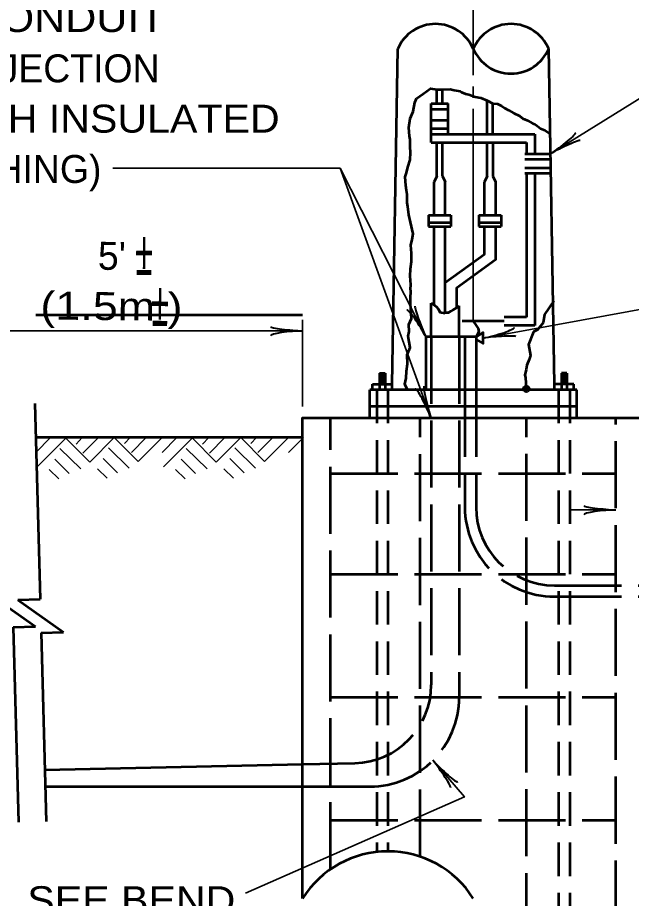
# Model space of a CAD drawing. Extents: x -68 to 612, y -58 to 382.
# Drawn here: x 153.4 to 208.3, y 135 to 213.8 of the extents above; entities that cross this region are included whole.
import ezdxf
from ezdxf.enums import TextEntityAlignment as Align

# ---------------------------------------------------------------- set-up
doc = ezdxf.new("R2010")
doc.units = 0
doc.header["$PDMODE"] = 32
doc.header["$PDSIZE"] = 0.5
doc.linetypes.add('LONG_DASHED', pattern=[7.5, 6, -1.5])
doc.linetypes.add('MEDIUM_DASHED', pattern=[4.5, 3, -1.5])
doc.layers.add('1', color=7, linetype='Continuous', lineweight=53)

msp = doc.modelspace()

# ---------------------------------------------------------------- linework, layer by layer
at = {"layer": '1', "lineweight": 35}
for p, q in [((194.116, 223.64), (194.116, 208.64)), ((194.116, 207.64), (194.116, 206.64)), ((194.116, 205.64), (194.116, 186.64)), ((182.206, 200.326), (161.911, 200.326)), ((195.016, 185.14), (221.485, 189.97)), ((178.866, 179.015), (178.866, 186.775)), ((147.007, 185.775), (178.866, 185.775)), ((156.327, 176.235), (155.007, 174.915)), ((157.747, 176.235), (155.127, 173.615)), ((157.647, 176.235), (159.847, 174.035)), ((159.167, 176.235), (158.607, 175.655)), ((160.607, 176.235), (159.227, 174.855)), ((162.027, 176.235), (159.847, 174.035)), ((162.027, 176.235), (164.167, 174.095)), ((163.447, 176.235), (162.927, 175.715)), ((164.887, 176.235), (163.567, 174.915)), ((166.307, 176.235), (164.167, 174.095)), ((167.627, 176.235), (166.307, 174.915)), ((169.047, 176.235), (166.427, 173.615)), ((168.947, 176.235), (171.147, 174.035)), ((170.467, 176.235), (169.907, 175.655)), ((171.907, 176.235), (170.527, 174.855)), ((173.327, 176.235), (171.147, 174.035)), ((173.327, 176.235), (175.467, 174.095)), ((174.747, 176.235), (174.227, 175.715)), ((176.187, 176.235), (174.867, 174.915)), ((177.607, 176.235), (175.467, 174.095)), ((178.927, 176.235), (177.607, 174.915)), ((157.167, 175.275), (159.027, 173.435)), ((161.507, 175.335), (163.347, 173.495)), ((168.467, 175.275), (170.327, 173.435)), ((172.807, 175.335), (174.647, 173.495)), ((156.707, 174.315), (157.987, 173.035)), ((161.047, 174.375), (162.327, 173.095)), ((168.007, 174.315), (169.287, 173.035)), ((172.347, 174.375), (173.627, 173.095)), ((156.207, 173.395), (157.067, 172.555)), ((160.527, 173.455), (161.387, 172.595)), ((167.507, 173.395), (168.367, 172.555)), ((171.827, 173.455), (172.687, 172.595)), ((206.866, 169.764), (202.866, 169.764))]:
    msp.add_line(p, q, dxfattribs=at)
at = {"layer": '1'}
for p, q in [((186.866, 181.015), (187.366, 211.015)), ((201.366, 181.015), (200.866, 211.015)), ((190.866, 206.126), (190.866, 207.376)), ((191.366, 206.126), (191.366, 207.376)), ((190.366, 202.626), (190.366, 206.126)), ((190.366, 206.126), (191.866, 206.126)), ((190.366, 205.626), (191.866, 205.626)), ((191.866, 203.376), (191.866, 206.126)), ((195.366, 203.376), (195.366, 206.376)), ((195.866, 203.376), (195.866, 206.126)), ((190.366, 204.623), (191.866, 204.623)), ((190.366, 203.876), (191.866, 203.876)), ((190.366, 203.376), (199.616, 203.376)), ((199.616, 203.376), (199.616, 201.626)), ((190.366, 202.626), (198.866, 202.626)), ((190.866, 199.626), (190.866, 202.626)), ((191.366, 199.626), (191.366, 202.626)), ((195.366, 199.626), (195.366, 202.626)), ((195.866, 202.626), (195.866, 199.626)), ((198.866, 202.626), (198.866, 201.626)), ((198.741, 201.626), (201.023, 201.626)), ((198.741, 201.126), (201.023, 201.126)), ((198.741, 200.376), (201.023, 200.376)), ((190.866, 199.626), (190.616, 199.126)), ((191.366, 199.626), (191.616, 199.126)), ((195.366, 199.626), (195.116, 199.126)), ((195.866, 199.626), (196.116, 199.126)), ((198.741, 199.876), (201.023, 199.876)), ((198.866, 199.876), (198.866, 187.015)), ((199.616, 199.876), (199.616, 186.265)), ((190.616, 196.126), (190.616, 199.126)), ((191.616, 196.126), (191.616, 199.126)), ((195.116, 196.126), (195.116, 199.126)), ((196.116, 199.126), (196.116, 196.126)), ((190.116, 196.126), (192.116, 196.126)), ((190.116, 196.126), (190.116, 195.126)), ((190.116, 195.47), (192.116, 195.47)), ((192.116, 196.126), (192.116, 195.126)), ((194.616, 196.126), (196.616, 196.126)), ((194.616, 196.126), (194.616, 195.126)), ((194.616, 195.47), (196.616, 195.47)), ((196.616, 196.126), (196.616, 195.126)), ((190.116, 195.126), (190.616, 195.126)), ((190.616, 195.126), (192.116, 195.126)), ((190.616, 188.122), (190.616, 195.126)), ((191.616, 187.381), (191.616, 195.126)), ((194.616, 195.126), (195.116, 195.126)), ((190.366, 185.265), (190.366, 188.265)), ((192.616, 187.848), (192.866, 188.015)), ((192.866, 185.265), (192.866, 188.015)), ((155.007, 187.207), (178.866, 187.207)), ((198.866, 187.015), (196.866, 187.015)), ((196.866, 186.64), (193.116, 186.64)), ((199.616, 186.265), (196.866, 186.265)), ((193.366, 185.265), (193.366, 180.515)), ((194.366, 185.265), (194.366, 180.515)), ((185.741, 182.015), (185.741, 180.515)), ((185.741, 182.015), (186.241, 182.015)), ((186.241, 182.015), (186.241, 180.515)), ((201.991, 182.015), (201.991, 180.515)), ((202.491, 182.015), (201.991, 182.015)), ((202.491, 182.015), (202.491, 180.515)), ((185.741, 181.765), (186.241, 181.765)), ((185.741, 181.515), (186.241, 181.515)), ((185.741, 181.265), (186.241, 181.265)), ((185.866, 181.89), (186.116, 181.89)), ((185.866, 181.64), (186.116, 181.64)), ((185.866, 181.39), (186.116, 181.39)), ((202.491, 181.765), (201.991, 181.765)), ((202.491, 181.515), (201.991, 181.515)), ((202.491, 181.265), (201.991, 181.265)), ((202.366, 181.89), (202.116, 181.89)), ((202.366, 181.64), (202.116, 181.64)), ((202.366, 181.39), (202.116, 181.39)), ((184.866, 178.015), (184.866, 180.515)), ((203.366, 180.515), (184.866, 180.515)), ((185.116, 180.515), (185.116, 181.015)), ((185.116, 181.015), (186.866, 181.015)), ((185.866, 181.14), (186.116, 181.14)), ((186.866, 180.515), (186.866, 181.015)), ((201.366, 180.515), (201.366, 181.015)), ((203.116, 181.015), (201.366, 181.015)), ((202.366, 181.14), (202.116, 181.14)), ((203.116, 180.515), (203.116, 181.015)), ((203.366, 178.015), (203.366, 180.515)), ((154.925, 179.274), (155.406, 161.775)), ((203.366, 179.015), (184.866, 179.015)), ((155.007, 176.275), (178.866, 176.275)), ((150.893, 162.22), (154.974, 159.331)), ((153.406, 161.72), (155.406, 161.775)), ((153.406, 161.72), (157.487, 158.831)), ((152.974, 159.276), (154.974, 159.331)), ((152.974, 159.276), (153.454, 141.839)), ((155.488, 158.776), (157.487, 158.831)), ((155.488, 158.776), (155.952, 141.908)), ((155.825, 146.525), (178.866, 147.025)), ((155.866, 145.025), (178.866, 145.025))]:
    msp.add_line(p, q, dxfattribs=at)
at = {"layer": '1', "linetype": 'LONG_DASHED'}
for p, q in [((190.366, 185.265), (190.366, 154.125)), ((192.866, 185.265), (192.866, 153.025)), ((193.366, 180.515), (193.366, 170.015)), ((194.366, 180.515), (194.366, 170.015)), ((181.366, 137.634), (181.366, 178.015)), ((189.366, 138.762), (189.366, 178.015)), ((198.866, 131.289), (198.866, 178.015)), ((206.866, 132.417), (206.866, 178.015)), ((181.366, 173.015), (206.866, 173.015)), ((181.366, 164.015), (206.866, 164.015)), ((201.366, 163.015), (209.366, 163.015)), ((201.366, 162.015), (209.366, 162.015)), ((181.366, 153.015), (206.866, 153.015)), ((178.866, 147.025), (183.518, 147.126)), ((178.866, 145.025), (184.866, 145.025)), ((181.366, 142.015), (206.866, 142.015))]:
    msp.add_line(p, q, dxfattribs=at)
at = {"layer": '1', "linetype": 'MEDIUM_DASHED'}
for p, q in [((185.491, 180.515), (185.491, 139.177)), ((186.491, 180.515), (186.491, 139.233)), ((201.741, 180.515), (201.741, 130.818)), ((202.741, 180.515), (202.741, 130.873))]:
    msp.add_line(p, q, dxfattribs=at)
at = {"layer": '1', "lineweight": 35}
for points in [[(201.023, 201.626), (213.267, 209.222), (216.001, 209.222)], [(189.866, 185.265), (182.206, 200.326), (190.322, 178.015)], [(190.523, 147.369), (193.33, 144.099), (173.761, 135.499)]]:
    msp.add_lwpolyline(points, dxfattribs=at)
at = {"layer": '1'}
for points in [[(188.233, 180.517), (188.001, 181.02), (188.117, 181.561), (188.156, 182.179), (188.233, 182.836), (188.194, 183.648), (188.465, 184.305), (188.31, 185.309), (188.387, 185.734), (188.349, 186.353), (188.581, 186.894), (188.503, 188.208), (188.503, 188.71), (188.542, 189.328), (188.503, 189.522), (188.542, 189.908), (188.503, 190.333), (188.465, 190.681), (188.503, 191.338), (188.581, 191.995), (188.581, 192.729), (188.542, 193.463), (188.658, 193.966), (188.735, 194.468), (188.503, 195.511), (188.349, 196.168), (188.272, 196.903), (188.194, 197.25), (188.194, 197.985), (188.156, 198.332), (188.078, 198.796), (188.04, 199.569), (188.156, 199.917), (188.272, 200.419), (188.465, 201.076), (188.503, 201.733), (188.465, 202.236), (188.465, 202.892), (188.426, 203.202), (188.349, 203.975), (188.465, 204.786), (188.735, 205.404), (188.89, 206.216), (189.044, 206.564), (189.624, 206.989), (190.28, 207.452), (190.866, 207.376), (191.366, 207.376), (192.057, 207.414), (192.405, 207.298), (192.946, 207.221), (193.062, 207.143), (193.409, 206.989), (193.719, 206.911), (194.298, 206.718), (194.8, 206.641), (195.366, 206.376), (195.866, 206.126), (196.268, 206.1), (196.655, 205.907), (196.925, 205.713), (197.273, 205.52), (197.736, 205.25), (198.238, 205.018), (198.586, 204.747), (198.702, 204.709), (198.972, 204.593), (199.436, 204.322), (199.629, 204.284), (199.822, 204.129), (200.131, 203.897), (200.518, 203.743), (200.904, 203.472)], [(192.616, 187.839), (192.334, 187.678), (192.113, 187.54), (191.865, 187.402), (191.616, 187.402), (191.616, 190.117), (195.116, 192.638), (195.116, 195.126)], [(195.116, 195.126), (196.116, 195.126), (196.116, 192.126), (192.616, 189.605), (192.616, 187.855)], [(195.116, 195.126), (196.116, 195.126), (196.616, 195.126)], [(201.329, 188.478), (200.479, 187.242), (200.363, 186.507), (199.861, 185.889), (199.513, 185.696), (199.05, 184.575), (199.243, 183.57), (199.127, 183.223), (198.895, 182.72), (198.857, 182.334), (198.741, 181.831), (198.779, 181.6), (198.857, 180.595)], [(190.366, 188.265), (190.649, 188.093), (190.87, 187.899), (190.925, 187.816), (191.008, 187.733), (191.119, 187.457), (191.616, 187.381)], [(194.116, 186.64), (194.377, 186.266), (194.549, 185.999), (194.606, 185.692), (194.366, 185.265)], [(194.366, 185.265), (189.866, 185.265), (189.866, 180.515)], [(178.866, 135.025), (178.866, 178.015), (209.366, 178.015)]]:
    msp.add_lwpolyline(points, dxfattribs=at)
msp.add_lwpolyline([(194.366, 185.265), (194.366, 185.015), (195.016, 184.64), (195.016, 185.64)], close=True, dxfattribs=at)
for centre, radius, start, end in [((190.741, 209.558), 3.676, 23.35021, 156.64979), ((197.491, 209.558), 3.676, 23.35021, 156.64979), ((197.491, 212.472), 3.676, 203.35021, 336.64979), ((186.491, 130.22), 9.013, 32.21778, 147.78221)]:
    msp.add_arc(centre, radius, start, end, dxfattribs=at)
at = {"layer": '1', "linetype": 'LONG_DASHED'}
for centre, radius, start, end in [((201.366, 170.015), 8, 180, 270), ((201.366, 170.015), 7, 180, 270), ((183.366, 154.125), 7, 271.24401, 0), ((184.866, 153.025), 8, 270, 0)]:
    msp.add_arc(centre, radius, start, end, dxfattribs=at)
at = {"layer": '1', "lineweight": 40}
for centre, major_axis, ratio, start_param, end_param in [((201.804, 202.436), (-1.435, -1.074), 0.122415, 0.896353, 3.141593), ((202.086, 202.037), (1.585, 0.777), 0.07063, 6.282307, 8.559703), ((189.125, 186.112), (0.949, -1.521), 0.122415, 0.896353, 3.141593), ((189.125, 186.112), (0.949, -1.521), 0.122415, 0.896353, 3.141593), ((189.547, 186.359), (0.64, -1.645), 0.07063, 3.140715, 5.41811), ((189.547, 186.359), (0.64, -1.645), 0.07063, 3.140715, 5.41811), ((177.746, 185.987), (1.756, -0.176), 0.07063, 3.140715, 5.41811), ((177.746, 185.987), (1.756, -0.176), 0.07063, 3.140715, 5.41811), ((196.04, 185.607), (-1.729, -0.474), 0.122415, 0.896353, 3.141593), ((196.04, 185.607), (-1.729, -0.474), 0.122415, 0.896353, 3.141593), ((177.775, 185.499), (1.786, 0.156), 0.122415, 0.896353, 3.141593), ((177.775, 185.499), (1.786, 0.156), 0.122415, 0.896353, 3.141593), ((196.156, 185.133), (-1.759, -0.143), 0.07063, 3.140715, 5.41811), ((196.156, 185.133), (-1.759, -0.143), 0.07063, 3.140715, 5.41811), ((189.689, 178.946), (0.757, -1.625), 0.122415, 0.896353, 3.141593), ((189.689, 178.946), (0.757, -1.625), 0.122415, 0.896353, 3.141593), ((190.138, 179.14), (-0.435, 1.711), 0.07063, 6.282307, 8.559703), ((190.138, 179.14), (-0.435, 1.711), 0.07063, 6.282307, 8.559703), ((205.775, 169.488), (1.786, 0.156), 0.122415, 0.896353, 3.141593), ((205.775, 169.488), (1.786, 0.156), 0.122415, 0.896353, 3.141593), ((205.746, 169.976), (1.756, -0.176), 0.07063, 3.140715, 5.41811), ((205.746, 169.976), (1.756, -0.176), 0.07063, 3.140715, 5.41811), ((191.092, 146.381), (-1.011, 1.447), 0.07063, 3.140715, 5.41811), ((191.092, 146.381), (-1.011, 1.447), 0.07063, 3.140715, 5.41811), ((191.443, 146.721), (-1.282, 1.253), 0.122415, 0.896353, 3.141593), ((191.443, 146.721), (-1.282, 1.253), 0.122415, 0.896353, 3.141593)]:
    msp.add_ellipse(centre, major_axis=major_axis, ratio=ratio, start_param=start_param, end_param=end_param, dxfattribs=at)
at = {"layer": '1'}
msp.add_point((198.857, 180.595), dxfattribs=at)

# ---------------------------------------------------------------- texts
for s, width, p in [('4" CONDUIT', 1.15, (144.532, 212.513)), ('(WITH INSULATED', 1.1, (144.532, 203.513)), ('SEE BEND', 1.1, (154.249, 133.612))]:
    msp.add_text(s, height=2.5, dxfattribs=dict(at, width=width)).set_placement(p)
for s, p in [('PROJECTION', (144.532, 208.013)), ('BUSHING)', (144.532, 199.013))]:
    msp.add_text(s, height=2.5, dxfattribs=at).set_placement(p)
for s, height, width, p in [('+', 4, 0.55, (164.679, 190.818)), ('(1.5m )', 2.5, 1.2, (161.763, 186.742)), ('+', 4, 0.55, (166.095, 186.271))]:
    msp.add_text(s, height=height, rotation=359.477, dxfattribs=dict(at, width=width)).set_placement(p, align=Align.CENTER)
for s, height, p in [("5'", 2.5, (161.804, 191.242)), ('-', 4, (164.671, 189.458)), ('-', 4, (166.087, 184.911))]:
    msp.add_text(s, height=height, rotation=359.477, dxfattribs=at).set_placement(p, align=Align.CENTER)

doc.saveas('drawing.dxf')
